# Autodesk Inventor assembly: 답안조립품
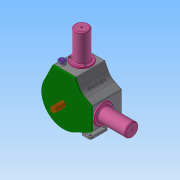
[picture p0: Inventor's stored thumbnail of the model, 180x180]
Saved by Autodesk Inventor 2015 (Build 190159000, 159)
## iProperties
Created: 2022-01
Part Number: 답안조립품
Document SubType Name: Assembly
Designer: user
Mass: 3748.68 g
Surface Area: 4101.78 cm^2
Volume: 1119.43 cm^3
Density: 3.34872 g/cm^3
Author: user
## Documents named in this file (13)
- C:\Users\user\Desktop\620117V1002\답안조립품.iam
- C:\Users\user\Desktop\620117V1002\너트 M3.ipt
- C:\Users\user\Desktop\620117V1002\베어링 20 x 37 x 9.ipt
- C:\Users\user\Desktop\620117V1002\본체.ipt
- C:\Users\user\Desktop\620117V1002\볼트 M3 x 12.ipt
- C:\Users\user\Desktop\620117V1002\실린더.ipt
- C:\Users\user\Desktop\620117V1002\앞커버.ipt
- C:\Users\user\Desktop\620117V1002\축.ipt
- C:\Users\user\Desktop\620117V1002\측정게이지.ipt
- C:\Users\user\Desktop\620117V1002\커넥팅로드 캡.ipt
- C:\Users\user\Desktop\620117V1002\커넥팅로드.ipt
- C:\Users\user\Desktop\620117V1002\피스톤 핀.ipt
- C:\Users\user\Desktop\620117V1002\피스톤.ipt
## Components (4 placed, 2 different names)
1. 피스톤 핀:1 — 플러쉬:1
2. 피스톤:1
3. 피스톤:2 — 플러쉬:2
4. 피스톤 핀:2
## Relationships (2: Flush 2)
- 플러쉬:1 [Flush]: 피스톤 핀:1
- 플러쉬:2 [Flush]: 피스톤:2
